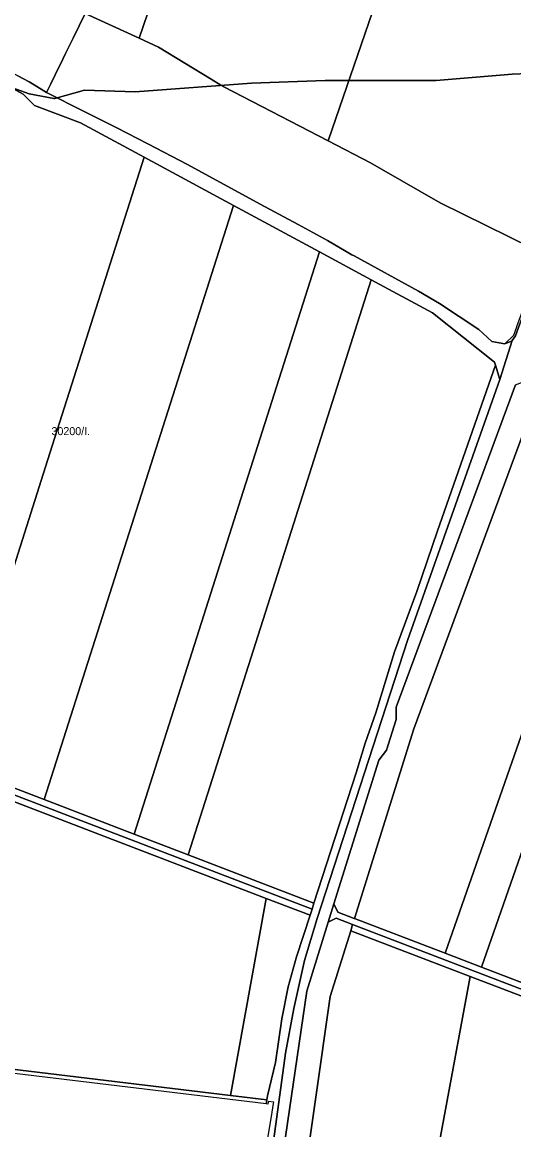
# Model space of a CAD drawing. Extents: x -545779 to -541342, y -1153413 to -1149956.
# Drawn here: x -545020 to -544713, y -1152954 to -1152262 of the extents above; entities that cross this region are included whole.
import ezdxf

# ---------------------------------------------------------------- set-up
doc = ezdxf.new("R2010")
doc.units = 0
for name, color, linetype in [('95560013', 7, 'Continuous'), ('95640013', 7, 'Continuous'), ('95660013', 7, 'Continuous')]:
    doc.layers.add(name, color=color, linetype=linetype)

msp = doc.modelspace()

# ---------------------------------------------------------------- linework, layer by layer
at = {"layer": '95560013'}
for points in [[(-544842.54, -1151966.01), (-544894.95, -1152119.02), (-544947.32, -1152271.94), (-544981.08, -1152256.44), (-544992.95, -1152248.71), (-545005.27, -1152243.89), (-545017.89, -1152238.96), (-545038.6, -1152230.87), (-545067.38, -1152219.63), (-545089.98, -1152210.8), (-545041.06, -1152067.96), (-544992.14, -1151925.13)], [(-544902.29, -1152297.51), (-544935.3, -1152277.46), (-544947.32, -1152271.94), (-544894.95, -1152119.02), (-544842.54, -1151966.01), (-544714.36, -1152001.03), (-544771.74, -1152168.57), (-544829.11, -1152336.09), (-544894.29, -1152302.21), (-544896.18, -1152301.23)], [(-544829.11, -1152336.09), (-544771.74, -1152168.57), (-544714.36, -1152001.03), (-544570.31, -1152040.39), (-544599.8, -1152126.71), (-544609.92, -1152155.93), (-544651.83, -1152276.93), (-544699.22, -1152404.28), (-544701.77, -1152403.03), (-544759.32, -1152374.84), (-544795.95, -1152353.72), (-544802.85, -1152349.74)], [(-544983.88, -1152324.78), (-544944.14, -1152346.23), (-545004.48, -1152535.78), (-545064.82, -1152725.34), (-545169.1, -1152685.33), (-545127.54, -1152554.75), (-545085.97, -1152424.16), (-545044.41, -1152293.58), (-545019.73, -1152306.85), (-545012.67, -1152314.02)], [(-545064.82, -1152725.34), (-545004.48, -1152535.78), (-544944.14, -1152346.23), (-544888.36, -1152376.35), (-544947.46, -1152562.02), (-545006.56, -1152747.69)], [(-544947.46, -1152562.02), (-544888.36, -1152376.35), (-544834.56, -1152405.4), (-544892.46, -1152587.33), (-544950.37, -1152769.26), (-545006.56, -1152747.69)], [(-544834.56, -1152405.4), (-544802.23, -1152422.86), (-544859.42, -1152602.54), (-544916.61, -1152782.21), (-544950.37, -1152769.26), (-544892.46, -1152587.33)], [(-544725.21, -1152474.29), (-544724.67, -1152476.17), (-544760.95, -1152579.73), (-544773.83, -1152617.6), (-544787.72, -1152655.4), (-544799.48, -1152693.58), (-544806.14, -1152712.45), (-544811.64, -1152731), (-544838.05, -1152812.35), (-544916.61, -1152782.21), (-544859.42, -1152602.54), (-544802.23, -1152422.86), (-544764.06, -1152443.46)], [(-544812.66, -1152822.07), (-544775.66, -1152703.45), (-544736.56, -1152597.62), (-544697.46, -1152491.78), (-544676.91, -1152502.94), (-544664.42, -1152509.45), (-544642.93, -1152519.54), (-544699.47, -1152681.65), (-544756.01, -1152843.76)], [(-544733.41, -1152852.41), (-544756.01, -1152843.76), (-544699.47, -1152681.65), (-544642.93, -1152519.54), (-544631.29, -1152525.01), (-544621.12, -1152530.46), (-544677.26, -1152691.43)], [(-544617.01, -1152532.67), (-544596.19, -1152545.83), (-544651.44, -1152704.24), (-544706.69, -1152862.64), (-544733.41, -1152852.41), (-544677.26, -1152691.43), (-544621.12, -1152530.46)], [(-545094.16, -1152907.97), (-545087.05, -1152725.38), (-544977.49, -1152767.41), (-544867.94, -1152809.45), (-544890.18, -1152932.58), (-544992.14, -1152920.28)], [(-544867.1, -1152932.9), (-544867.51, -1152935.32), (-544890.18, -1152932.58), (-544867.94, -1152809.45), (-544840.53, -1152819.97), (-544848.97, -1152845.97), (-544854.21, -1152864.7), (-544858.05, -1152884.78), (-544862.06, -1152911.98)], [(-544827.86, -1152870.81), (-544815.05, -1152829.72), (-544740.52, -1152858.26), (-544767.53, -1153004.26), (-544794.54, -1153150.25), (-544864.36, -1153125.27), (-544846.11, -1152998.04)], [(-544767.53, -1153004.26), (-544740.52, -1152858.26), (-544664.13, -1152887.48), (-544690.97, -1153032.58), (-544717.82, -1153177.69), (-544794.54, -1153150.25)]]:
    msp.add_lwpolyline(points, close=True, dxfattribs=at)
at = {"layer": '95640013'}
for points in [[(-544869.92, -1153010.12), (-544855.89, -1152906.13), (-544850.74, -1152878.22), (-544843.92, -1152848.27), (-544835.97, -1152822.11), (-544779.71, -1152648.34), (-544722.02, -1152485.29), (-544714.17, -1152460.73), (-544712.17, -1152457.99), (-544710.26, -1152452.68), (-544705.98, -1152440.77), (-544704.95, -1152437.89), (-544700.68, -1152426), (-544695.87, -1152412.62), (-544696.71, -1152410.52), (-544630.44, -1152231.35)], [(-544981.08, -1152256.44), (-544988.58, -1152271.82), (-544993.28, -1152281.45), (-544995.02, -1152285.01), (-544999.74, -1152294.69), (-545002.71, -1152300.77), (-545005.16, -1152305.8), (-545005.28, -1152305.8), (-545012.93, -1152301.13), (-545015.99, -1152299.27), (-545023.01, -1152295.52), (-545027.26, -1152293.25), (-545035.06, -1152288.88), (-545049, -1152281.07), (-545054.69, -1152277.97), (-545070.9, -1152269.17), (-545082.1, -1152262.99), (-545092.74, -1152257.13)], [(-544713.1, -1152457.38), (-544718.92, -1152462.93), (-544722.41, -1152462.33), (-544726.95, -1152461.54), (-544735.08, -1152453.88), (-544759.6, -1152437.75), (-544772.72, -1152430.09), (-544812.99, -1152408), (-544814.36, -1152407.19), (-544829.52, -1152398.25), (-544847.95, -1152388.29), (-544871.71, -1152375.59), (-544916.99, -1152350.83), (-544941.85, -1152337.92), (-544961.14, -1152327.91), (-544965.36, -1152325.79), (-544982.08, -1152317.42), (-545005.28, -1152305.8), (-545005.16, -1152305.8), (-545002.71, -1152300.77), (-544999.74, -1152294.69), (-544995.02, -1152285.01), (-544993.28, -1152281.45), (-544988.58, -1152271.82), (-544981.08, -1152256.44), (-544947.32, -1152271.94), (-544935.3, -1152277.46), (-544902.29, -1152297.51), (-544896.18, -1152301.23), (-544894.29, -1152302.21), (-544829.11, -1152336.09), (-544802.85, -1152349.74), (-544795.95, -1152353.72), (-544759.32, -1152374.84), (-544701.77, -1152403.03)], [(-545023.01, -1152295.52), (-545015.99, -1152299.27), (-545012.93, -1152301.13), (-545005.28, -1152305.8), (-544982.08, -1152317.42), (-544965.36, -1152325.79), (-544961.14, -1152327.91), (-544941.85, -1152337.92), (-544916.99, -1152350.83), (-544871.71, -1152375.59), (-544847.95, -1152388.29), (-544829.52, -1152398.25), (-544814.36, -1152407.19), (-544812.99, -1152408), (-544772.72, -1152430.09), (-544759.6, -1152437.75), (-544735.08, -1152453.88), (-544726.95, -1152461.54), (-544722.41, -1152462.33), (-544718.92, -1152462.93), (-544714.6, -1152461.32), (-544714.17, -1152460.73), (-544722.02, -1152485.29), (-544724.67, -1152476.17), (-544725.21, -1152474.29), (-544764.06, -1152443.46), (-544802.23, -1152422.86), (-544834.56, -1152405.4), (-544888.36, -1152376.35), (-544944.14, -1152346.23), (-544983.88, -1152324.78), (-545012.67, -1152314.02), (-545019.73, -1152306.85), (-545044.41, -1152293.58)], [(-544892.65, -1153113.74), (-544864.7, -1152945.73), (-544863.34, -1152937.57), (-544863.21, -1152936.8), (-544866.69, -1152936.45), (-544866.77, -1152936.91), (-544866.95, -1152937.97), (-544867.93, -1152937.85), (-544867.51, -1152935.32), (-544867.1, -1152932.9), (-544862.06, -1152911.98), (-544858.05, -1152884.78), (-544854.21, -1152864.7), (-544848.97, -1152845.97), (-544840.53, -1152819.97), (-544839.29, -1152816.15), (-544838.05, -1152812.35), (-544811.64, -1152731), (-544806.14, -1152712.45), (-544799.48, -1152693.58), (-544787.72, -1152655.4), (-544773.83, -1152617.6), (-544760.95, -1152579.73), (-544724.67, -1152476.17), (-544722.02, -1152485.29), (-544779.71, -1152648.34), (-544835.97, -1152822.11), (-544843.92, -1152848.27), (-544850.74, -1152878.22), (-544855.89, -1152906.13), (-544869.92, -1153010.12)], [(-544712.22, -1152488.45), (-544749.46, -1152589.25), (-544786.7, -1152690.05), (-544786.64, -1152697.75), (-544792.82, -1152716.77), (-544797.52, -1152723.13), (-544825.61, -1152812.84), (-544829.15, -1152824.31), (-544842.53, -1152867.47), (-544871.48, -1153065.1)]]:
    msp.add_lwpolyline(points, dxfattribs=at)
for points in [[(-544711.26, -1152452.09), (-544706.94, -1152440.21), (-544705.9, -1152437.34), (-544701.58, -1152425.47), (-544701.54, -1152425.35), (-544697.22, -1152411.89), (-544699.22, -1152404.28), (-544696.71, -1152410.52), (-544695.87, -1152412.62), (-544700.68, -1152426), (-544704.95, -1152437.89), (-544705.98, -1152440.77), (-544710.26, -1152452.68), (-544712.17, -1152457.99), (-544714.17, -1152460.73), (-544714.6, -1152461.32), (-544718.92, -1152462.93), (-544713.1, -1152457.38), (-544711.37, -1152452.38)], [(-544812.87, -1152822), (-544823.15, -1152818.06), (-544825.61, -1152812.84), (-544797.52, -1152723.13), (-544792.82, -1152716.77), (-544786.64, -1152697.75), (-544786.7, -1152690.05), (-544749.46, -1152589.25), (-544712.22, -1152488.45), (-544707.28, -1152486.57), (-544697.46, -1152491.78), (-544736.56, -1152597.62), (-544775.66, -1152703.45), (-544812.66, -1152822.07)], [(-544839.29, -1152816.15), (-544980.99, -1152761.78), (-545122.7, -1152707.4), (-545264.4, -1152653.03), (-545406.1, -1152598.66), (-545407.51, -1152598.12), (-545413.99, -1152597.13), (-545409.26, -1152593.32), (-545408, -1152589.42), (-545405.38, -1152594.66), (-545322.32, -1152626.53), (-545279.35, -1152643.02), (-545169.1, -1152685.33), (-545064.82, -1152725.34), (-545006.56, -1152747.69), (-544950.37, -1152769.26), (-544916.61, -1152782.21), (-544838.05, -1152812.35)], [(-544840.53, -1152819.97), (-544867.94, -1152809.45), (-544977.49, -1152767.41), (-545087.05, -1152725.38), (-545248.54, -1152663.41), (-545355.58, -1152622.34), (-545402.66, -1152604.27), (-545411.28, -1152600.96), (-545406.1, -1152598.66), (-545264.4, -1152653.03), (-545122.7, -1152707.4), (-544980.99, -1152761.78), (-544839.29, -1152816.15)], [(-544824.27, -1152821.91), (-544829.15, -1152824.31), (-544825.61, -1152812.84), (-544823.15, -1152818.06), (-544812.87, -1152822), (-544812.66, -1152822.07), (-544756.01, -1152843.76), (-544733.41, -1152852.41), (-544706.69, -1152862.64), (-544647.63, -1152885.24), (-544614.11, -1152898.07), (-544592.95, -1152906.17), (-544570.91, -1152914.61), (-544534.74, -1152928.45), (-544478.02, -1152950.16), (-544306.21, -1153015.92), (-544289.61, -1153022.27), (-544284.5, -1153019.82), (-544287.34, -1153031.71), (-544290.33, -1153026.28), (-544464.89, -1152959.47), (-544639.44, -1152892.66), (-544814, -1152825.85)], [(-544827.86, -1152870.81), (-544846.11, -1152998.04), (-544864.36, -1153125.27), (-544874.79, -1153121.54), (-544878.23, -1153115.89), (-544871.48, -1153065.1), (-544842.53, -1152867.47), (-544829.15, -1152824.31), (-544824.27, -1152821.91), (-544814, -1152825.85), (-544815.05, -1152829.72)], [(-544610.94, -1152907.84), (-544664.13, -1152887.48), (-544740.52, -1152858.26), (-544815.05, -1152829.72), (-544814, -1152825.85), (-544639.44, -1152892.66), (-544464.89, -1152959.47), (-544290.33, -1153026.28), (-544287.34, -1153031.71), (-544313.08, -1153021.86), (-544339.15, -1153011.88), (-544363.26, -1153002.64), (-544376.19, -1152997.7), (-544389.6, -1152992.56), (-544479.75, -1152958.06)], [(-545528.77, -1152855.89), (-545519.64, -1152857), (-545490.7, -1152860.51), (-545435.26, -1152867.23), (-545413.01, -1152869.92), (-545365.44, -1152875.71), (-545257.3, -1152888.35), (-545094.16, -1152907.97), (-544992.14, -1152920.28), (-544890.18, -1152932.58), (-544867.51, -1152935.32), (-544867.93, -1152937.85), (-545053.11, -1152915.49), (-545254.16, -1152891.41), (-545431.89, -1152869.98), (-545629.47, -1152845.93), (-545629.43, -1152844.78), (-545629.39, -1152843.71), (-545596.45, -1152847.68), (-545551.84, -1152853.09)]]:
    msp.add_lwpolyline(points, close=True, dxfattribs=at)
at = {"layer": '95660013'}
for points in [[(-545039.364, -1152298.308), (-545016.094, -1152306.661), (-545000.581, -1152309.645), (-545000, -1152309.481), (-544981.489, -1152304.275), (-544949.866, -1152305.468), (-544877.074, -1152300.098), (-544831.132, -1152298.308), (-544814.52, -1152298.261), (-544761.625, -1152298.261), (-544714.241, -1152294.404), (-544626.083, -1152290.547)], [(-544626.083, -1152290.547), (-544714.241, -1152294.404), (-544761.625, -1152298.261), (-544814.52, -1152298.261), (-544831.132, -1152298.308), (-544877.074, -1152300.098), (-544949.866, -1152305.468), (-544981.489, -1152304.275), (-545000, -1152309.481), (-545000.581, -1152309.645), (-545016.094, -1152306.661), (-545039.364, -1152298.308)], [(-544892.65, -1153113.74), (-544864.7, -1152945.73), (-544863.34, -1152937.57), (-544863.21, -1152936.8), (-544866.69, -1152936.45), (-544866.77, -1152936.91), (-544866.95, -1152937.97), (-544867.93, -1152937.85), (-545053.11, -1152915.49)]]:
    msp.add_lwpolyline(points, dxfattribs=at)

# ---------------------------------------------------------------- texts
msp.add_text('30200/I.', height=5, rotation=360, dxfattribs=at).set_placement((-545002.079, -1152519.957))

doc.saveas('drawing.dxf')
